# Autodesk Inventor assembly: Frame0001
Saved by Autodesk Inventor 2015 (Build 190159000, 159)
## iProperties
Created: 2020-03
Part Number: Frame0001
Document SubType Name: Assembly
Designer: 徐冠倫
Mass: 2422.11 g
Surface Area: 2063.16 cm^2
Volume: 308.549 cm^3
Density: 7.85 g/cm^3
_FrameDoc: Frame Assembly
_Version: 15.0.0
Author: 徐冠倫
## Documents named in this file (4)
- C:\Users\徐冠倫\Desktop\Topic 13-2_框架分析(固定約束)\Topic 13-2_框架分析(固定約束)\Frame\Frame0001.iam
- C:\Users\徐冠倫\Desktop\Topic 13-2_框架分析(固定約束)\Topic 13-2_框架分析(固定約束)\Frame\Skeleton0001.ipt
- C:\Users\徐冠倫\Desktop\Topic 13-2_框架分析(固定約束)\Topic 13-2_框架分析(固定約束)\Frame\ISO 30x30x3 00000001.ipt
- ISO 30x30x3 00000001.ipt
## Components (2 placed, 2 different names)
1. Frame Reference Model
2. ISO 30x30x3 00000001:1
